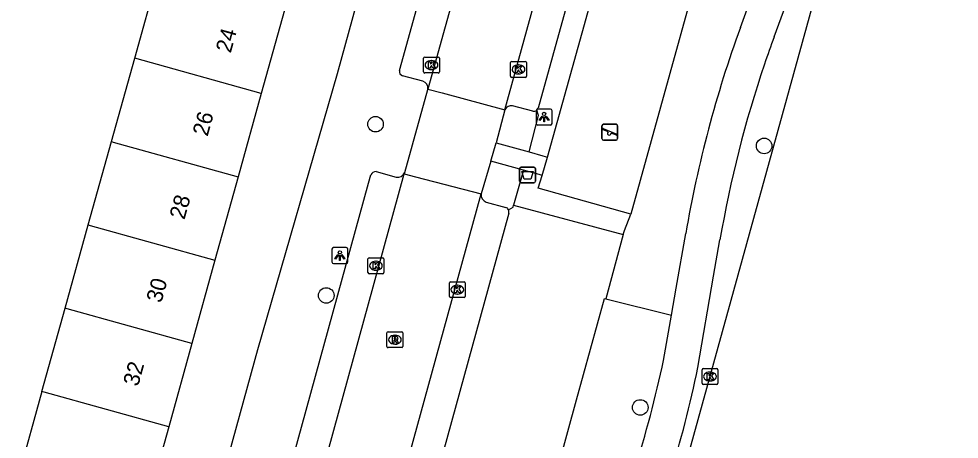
# Model space of a CAD drawing. Extents: x 162542 to 163144, y 380786 to 381511.
# Drawn here: x 163078.5 to 163137.6, y 381072.9 to 381099.3 of the extents above; entities that cross this region are included whole.
import ezdxf

# ---------------------------------------------------------------- set-up
doc = ezdxf.new("R2010")
doc.units = 0
for name, color, linetype in [('IMGEO_Afvalbak', 7, 'Continuous'), ('IMGEO_Berm_groen', 7, 'Continuous'), ('IMGEO_Boom', 7, 'Continuous'), ('IMGEO_Fietspad_gesloten', 7, 'Continuous'), ('IMGEO_Groenvoorziening', 7, 'Continuous'), ('IMGEO_Haag', 7, 'Continuous'), ('IMGEO_Hek', 7, 'Continuous'), ('IMGEO_Kolk', 7, 'Continuous'), ('IMGEO_Lichtpunt', 7, 'Continuous'), ('IMGEO_Pand', 7, 'Continuous'), ('IMGEO_Pand_nummerreeks', 7, 'Continuous'), ('IMGEO_Parkeervlak_open', 7, 'Continuous'), ('IMGEO_Rijbaan_lokaal_gesloten', 7, 'Continuous'), ('IMGEO_Rijbaan_lokaal_open', 7, 'Continuous'), ('IMGEO_Rioolput', 7, 'Continuous'), ('IMGEO_Speelvoorziening', 7, 'Continuous'), ('IMGEO_Voetpad_open', 7, 'Continuous')]:
    doc.layers.add(name, color=color, linetype=linetype)

msp = doc.modelspace()

# ---------------------------------------------------------------- linework, layer by layer
at = {"layer": 'IMGEO_Afvalbak'}
for p, q in [((163110.084, 381089.983), (163110.874, 381089.983)), ((163110.874, 381089.983), (163110.084, 381089.983)), ((163109.984, 381089.083), (163109.984, 381089.883)), ((163109.984, 381089.883), (163109.984, 381089.083)), ((163110.974, 381089.883), (163110.974, 381089.083)), ((163110.974, 381089.083), (163110.974, 381089.883)), ((163110.874, 381088.983), (163110.084, 381088.983)), ((163110.084, 381088.983), (163110.874, 381088.983))]:
    msp.add_line(p, q, dxfattribs=at)
msp.add_lwpolyline([(163110.127, 381089.697), (163110.831, 381089.697), (163110.682, 381089.227), (163110.276, 381089.227), (163110.127, 381089.697)], dxfattribs=at)
for centre, start, end in [((163110.084, 381089.883), 90, 180), ((163110.084, 381089.883), 90, 180), ((163110.874, 381089.883), 0, 90), ((163110.874, 381089.883), 360, 90), ((163110.084, 381089.083), 180, 270), ((163110.084, 381089.083), 180, 270), ((163110.874, 381089.083), 270, 0), ((163110.874, 381089.083), 270, 0)]:
    msp.add_arc(centre, 0.1, start, end, dxfattribs=at)
at = {"layer": 'IMGEO_Berm_groen'}
for points in [[(163123.149, 381109.351), (163116.979, 381087.012)], [(163109.281, 381087.299), (163109.576, 381087.467), (163109.61, 381087.588)], [(163116.483, 381085.73), (163115.4, 381081.696)], [(163090.379, 381018.056), (163091.195, 381019.449), (163095.086, 381024.701), (163097.994, 381027.705), (163100.091, 381030.633), (163101.545, 381033.297), (163102.955, 381036.558), (163113.57, 381075.334), (163115.317, 381081.716), (163115.4, 381081.696)], [(163115.4, 381081.696), (163119.528, 381080.672)]]:
    msp.add_lwpolyline(points, dxfattribs=at)
at = {"layer": 'IMGEO_Boom'}
for centre in [(163100.929, 381092.677), (163125.353, 381091.31), (163097.833, 381081.902), (163117.566, 381074.858)]:
    msp.add_circle(centre, 0.489, dxfattribs=at)
at = {"layer": 'IMGEO_Fietspad_gesloten'}
for points in [[(163123.86, 381098.765), (163126.379, 381105.719)], [(163125.975, 381098.165), (163128.416, 381104.806)], [(163119.528, 381080.672), (163119.826, 381082.372), (163120.427, 381085.8)], [(163121.184, 381077.371), (163122.18, 381083.116), (163122.575, 381085.397)], [(163119.028, 381077.818), (163119.528, 381080.672)]]:
    msp.add_lwpolyline(points, dxfattribs=at)
for centre, radius, start, end in [((163194.822, 381073.038), 75.482, 160.07208, 170.26597), ((163197.67, 381072.049), 76.304, 159.98479, 161.34559), ((163194.995, 381072.943), 73.483, 161.33919, 170.24235), ((163044.442, 381093.779), 76.275, 337.20621, 347.92112), ((163053.246, 381091.16), 69.323, 336.76744, 348.52643)]:
    msp.add_arc(centre, radius, start, end, dxfattribs=at)
at = {"layer": 'IMGEO_Groenvoorziening'}
for points in [[(163111.735, 381090.612), (163117.414, 381111.017)], [(163110.596, 381090.932), (163111.18, 381093.228), (163111.063, 381093.558)]]:
    msp.add_lwpolyline(points, dxfattribs=at)
at = {"layer": 'IMGEO_Haag'}
for points in [[(163110.227, 381089.781), (163109.61, 381087.588)], [(163116.979, 381087.012), (163111.158, 381088.662), (163111.393, 381089.458)], [(163109.61, 381087.588), (163116.483, 381085.73)], [(163116.483, 381085.73), (163116.579, 381085.993), (163116.979, 381087.012)]]:
    msp.add_lwpolyline(points, dxfattribs=at)
at = {"layer": 'IMGEO_Hek'}
for points in [[(163111.735, 381090.612), (163117.414, 381111.017), (163123.149, 381109.351)], [(163123.149, 381109.351), (163116.979, 381087.012)], [(163116.979, 381087.012), (163111.158, 381088.662), (163111.393, 381089.458)]]:
    msp.add_lwpolyline(points, dxfattribs=at)
at = {"layer": 'IMGEO_Kolk'}
for p, q in [((163103.947, 381095.972), (163103.947, 381096.824)), ((163104.022, 381096.898), (163104.874, 381096.898)), ((163104.435, 381096.678), (163104.46, 381096.678)), ((163104.948, 381096.824), (163104.948, 381095.972)), ((163109.415, 381095.698), (163109.415, 381096.55)), ((163109.49, 381096.624), (163110.342, 381096.624)), ((163110.416, 381096.55), (163110.416, 381095.698)), ((163104.874, 381095.898), (163104.022, 381095.898)), ((163104.458, 381096.118), (163104.433, 381096.118)), ((163109.903, 381096.404), (163109.928, 381096.404)), ((163110.342, 381095.624), (163109.49, 381095.624)), ((163109.926, 381095.844), (163109.901, 381095.844)), ((163100.456, 381083.346), (163100.456, 381084.198)), ((163100.531, 381084.272), (163101.383, 381084.272)), ((163100.944, 381084.052), (163100.969, 381084.052)), ((163101.457, 381084.198), (163101.457, 381083.346)), ((163100.967, 381083.492), (163100.942, 381083.492)), ((163101.383, 381083.272), (163100.531, 381083.272)), ((163105.572, 381081.841), (163105.572, 381082.693)), ((163105.647, 381082.767), (163106.499, 381082.767)), ((163106.06, 381082.547), (163106.085, 381082.547)), ((163106.573, 381082.693), (163106.573, 381081.841)), ((163106.499, 381081.767), (163105.647, 381081.767)), ((163106.083, 381081.987), (163106.058, 381081.987)), ((163121.45, 381076.377), (163121.45, 381077.229)), ((163121.525, 381077.303), (163122.377, 381077.303)), ((163121.938, 381077.083), (163121.963, 381077.083)), ((163122.451, 381077.229), (163122.451, 381076.377)), ((163121.961, 381076.523), (163121.936, 381076.523)), ((163122.377, 381076.303), (163121.525, 381076.303))]:
    msp.add_line(p, q, dxfattribs=at)
for points in [[(163103.947, 381095.972), (163103.947, 381096.824)], [(163104.022, 381096.898), (163104.874, 381096.898)], [(163104.268, 381096.598), (163104.391, 381096.598), (163104.391, 381096.447), (163104.521, 381096.598), (163104.685, 381096.598), (163104.539, 381096.447), (163104.692, 381096.198), (163104.54, 381096.198), (163104.455, 381096.362), (163104.391, 381096.295), (163104.391, 381096.198), (163104.268, 381096.198), (163104.268, 381096.598)], [(163104.948, 381096.824), (163104.948, 381095.972)], [(163109.415, 381095.698), (163109.415, 381096.55)], [(163109.49, 381096.624), (163110.342, 381096.624)], [(163110.416, 381096.55), (163110.416, 381095.698)], [(163104.874, 381095.898), (163104.022, 381095.898)], [(163109.736, 381096.324), (163109.859, 381096.324), (163109.859, 381096.173), (163109.989, 381096.324), (163110.153, 381096.324), (163110.007, 381096.173), (163110.16, 381095.924), (163110.008, 381095.924), (163109.923, 381096.088), (163109.859, 381096.021), (163109.859, 381095.924), (163109.736, 381095.924), (163109.736, 381096.324)], [(163110.342, 381095.624), (163109.49, 381095.624)], [(163100.456, 381083.346), (163100.456, 381084.198)], [(163100.531, 381084.272), (163101.383, 381084.272)], [(163101.457, 381084.198), (163101.457, 381083.346)], [(163100.777, 381083.972), (163100.9, 381083.972), (163100.9, 381083.821), (163101.03, 381083.972), (163101.194, 381083.972), (163101.048, 381083.821), (163101.201, 381083.572), (163101.049, 381083.572), (163100.964, 381083.736), (163100.9, 381083.669), (163100.9, 381083.572), (163100.777, 381083.572), (163100.777, 381083.972)], [(163101.383, 381083.272), (163100.531, 381083.272)], [(163105.572, 381081.841), (163105.572, 381082.693)], [(163105.647, 381082.767), (163106.499, 381082.767)], [(163105.893, 381082.467), (163106.016, 381082.467), (163106.016, 381082.316), (163106.146, 381082.467), (163106.31, 381082.467), (163106.164, 381082.316), (163106.317, 381082.067), (163106.165, 381082.067), (163106.08, 381082.231), (163106.016, 381082.164), (163106.016, 381082.067), (163105.893, 381082.067), (163105.893, 381082.467)], [(163106.573, 381082.693), (163106.573, 381081.841)], [(163106.499, 381081.767), (163105.647, 381081.767)], [(163121.45, 381076.377), (163121.45, 381077.229)], [(163121.525, 381077.303), (163122.377, 381077.303)], [(163121.771, 381077.003), (163121.894, 381077.003), (163121.894, 381076.852), (163122.024, 381077.003), (163122.188, 381077.003), (163122.042, 381076.852), (163122.195, 381076.603), (163122.043, 381076.603), (163121.958, 381076.767), (163121.894, 381076.7), (163121.894, 381076.603), (163121.771, 381076.603), (163121.771, 381077.003)], [(163122.451, 381077.229), (163122.451, 381076.377)], [(163122.377, 381076.303), (163121.525, 381076.303)]]:
    msp.add_lwpolyline(points, dxfattribs=at)
for centre, start, end in [((163104.024, 381096.822), 91.55205, 178.44795), ((163104.024, 381096.822), 91.55205, 178.44795), ((163104.872, 381096.822), 1.55205, 88.44795), ((163104.872, 381096.822), 1.55205, 88.44795), ((163109.492, 381096.548), 91.55205, 178.44795), ((163109.492, 381096.548), 91.55205, 178.44795), ((163110.34, 381096.548), 1.55205, 88.44795), ((163110.34, 381096.548), 1.55205, 88.44795), ((163104.024, 381095.974), 181.55205, 268.44795), ((163104.024, 381095.974), 181.55205, 268.44795), ((163104.872, 381095.974), 271.55205, 358.44795), ((163104.872, 381095.974), 271.55205, 358.44795), ((163109.492, 381095.7), 181.55205, 268.44795), ((163109.492, 381095.7), 181.55205, 268.44795), ((163110.34, 381095.7), 271.55205, 358.44795), ((163110.34, 381095.7), 271.55205, 358.44795), ((163100.533, 381084.196), 91.55205, 178.44795), ((163100.533, 381084.196), 91.55205, 178.44795), ((163101.381, 381084.196), 1.55205, 88.44795), ((163101.381, 381084.196), 1.55205, 88.44795), ((163100.533, 381083.348), 181.55205, 268.44795), ((163100.533, 381083.348), 181.55205, 268.44795), ((163101.381, 381083.348), 271.55205, 358.44795), ((163101.381, 381083.348), 271.55205, 358.44795), ((163105.649, 381082.691), 91.55205, 178.44795), ((163105.649, 381082.691), 91.55205, 178.44795), ((163106.497, 381082.691), 1.55205, 88.44795), ((163106.497, 381082.691), 1.55205, 88.44795), ((163105.649, 381081.843), 181.55205, 268.44795), ((163105.649, 381081.843), 181.55205, 268.44795), ((163106.497, 381081.843), 271.55205, 358.44795), ((163106.497, 381081.843), 271.55205, 358.44795), ((163121.527, 381077.227), 91.55205, 178.44795), ((163121.527, 381077.227), 91.55205, 178.44795), ((163122.375, 381077.227), 1.55205, 88.44795), ((163122.375, 381077.227), 1.55205, 88.44795), ((163121.527, 381076.379), 181.55205, 268.44795), ((163121.527, 381076.379), 181.55205, 268.44795), ((163122.375, 381076.379), 271.55205, 358.44795), ((163122.375, 381076.379), 271.55205, 358.44795)]:
    msp.add_arc(centre, 0.0765, start, end, dxfattribs=at)
for centre, major_axis, ratio, start_param, end_param in [((163104.434, 381096.398), (-0.387, 0.002), 0.722429, 4.712389, 7.853982), ((163104.459, 381096.398), (-0.39, 0.002), 0.717154, 1.570796, 4.712389), ((163109.902, 381096.124), (-0.387, 0.002), 0.722429, 4.712389, 7.853982), ((163109.927, 381096.124), (-0.39, 0.002), 0.717154, 1.570796, 4.712389), ((163100.943, 381083.772), (-0.387, 0.002), 0.722429, 4.712389, 7.853982), ((163100.968, 381083.772), (-0.39, 0.002), 0.717154, 1.570796, 4.712389), ((163106.059, 381082.267), (-0.387, 0.002), 0.722429, 4.712389, 7.853982), ((163106.084, 381082.267), (-0.39, 0.002), 0.717154, 1.570796, 4.712389), ((163121.937, 381076.803), (-0.387, 0.002), 0.722429, 4.712389, 7.853982), ((163121.962, 381076.803), (-0.39, 0.002), 0.717154, 1.570796, 4.712389)]:
    msp.add_ellipse(centre, major_axis=major_axis, ratio=ratio, start_param=start_param, end_param=end_param, dxfattribs=at)
at = {"layer": 'IMGEO_Lichtpunt'}
for p, q in [((163111.026, 381093.528), (163111.026, 381092.721)), ((163111.026, 381093.528), (163111.026, 381092.721)), ((163111.928, 381093.623), (163111.12, 381093.623)), ((163111.928, 381093.623), (163111.12, 381093.623)), ((163112.022, 381092.721), (163112.022, 381093.528)), ((163112.022, 381092.721), (163112.022, 381093.528)), ((163111.12, 381092.627), (163111.928, 381092.627)), ((163111.12, 381092.627), (163111.928, 381092.627)), ((163098.192, 381084.816), (163098.192, 381084.009)), ((163098.192, 381084.816), (163098.192, 381084.009)), ((163099.094, 381084.911), (163098.286, 381084.911)), ((163099.094, 381084.911), (163098.286, 381084.911)), ((163099.188, 381084.009), (163099.188, 381084.816)), ((163099.188, 381084.009), (163099.188, 381084.816)), ((163098.286, 381083.915), (163099.094, 381083.915)), ((163098.286, 381083.915), (163099.094, 381083.915))]:
    msp.add_line(p, q, dxfattribs=at)
for points in [[(163111.4, 381093.192), (163111.439, 381093.164), (163111.251, 381092.902), (163111.213, 381092.929), (163111.4, 381093.192)], [(163111.502, 381093.144), (163111.549, 381093.144), (163111.549, 381092.822), (163111.502, 381092.822), (163111.502, 381093.144)], [(163111.612, 381093.164), (163111.65, 381093.191), (163111.837, 381092.929), (163111.798, 381092.901), (163111.612, 381093.164)], [(163098.566, 381084.48), (163098.605, 381084.452), (163098.417, 381084.19), (163098.379, 381084.217), (163098.566, 381084.48)], [(163098.668, 381084.432), (163098.715, 381084.432), (163098.715, 381084.11), (163098.668, 381084.11), (163098.668, 381084.432)], [(163098.778, 381084.452), (163098.816, 381084.479), (163099.003, 381084.217), (163098.964, 381084.189), (163098.778, 381084.452)]]:
    msp.add_lwpolyline(points, dxfattribs=at)
for centre in [(163111.525, 381093.326), (163098.691, 381084.614)]:
    msp.add_circle(centre, 0.0994, dxfattribs=at)
for centre, start, end in [((163111.12, 381093.528), 90, 180), ((163111.12, 381093.528), 90, 180), ((163111.928, 381093.528), 0, 90), ((163111.928, 381093.528), 0, 90), ((163111.12, 381092.721), 180, 270), ((163111.12, 381092.721), 180, 270), ((163111.928, 381092.721), 270, 0), ((163111.928, 381092.721), 270, 360), ((163098.286, 381084.816), 90, 180), ((163098.286, 381084.816), 90, 180), ((163099.094, 381084.816), 0, 90), ((163099.094, 381084.816), 0, 90), ((163098.286, 381084.009), 180, 270), ((163098.286, 381084.009), 180, 270), ((163099.094, 381084.009), 270, 0), ((163099.094, 381084.009), 270, 360)]:
    msp.add_arc(centre, 0.0946, start, end, dxfattribs=at)
at = {"layer": 'IMGEO_Pand'}
for points in [[(163085.795, 381096.822), (163087.252, 381102.063)], [(163095.205, 381099.852), (163093.75, 381094.611)], [(163084.339, 381091.582), (163085.795, 381096.822)], [(163093.75, 381094.611), (163085.795, 381096.822)], [(163093.75, 381094.611), (163092.295, 381089.37)], [(163082.882, 381086.341), (163084.339, 381091.582)], [(163084.339, 381091.582), (163084.441, 381091.554), (163092.295, 381089.37)], [(163092.295, 381089.37), (163090.84, 381084.129)], [(163081.426, 381081.1), (163082.882, 381086.341)], [(163082.882, 381086.341), (163082.997, 381086.309), (163090.84, 381084.129)], [(163090.84, 381084.129), (163089.386, 381078.888)], [(163079.969, 381075.86), (163081.426, 381081.1)], [(163089.386, 381078.888), (163081.553, 381081.065), (163081.426, 381081.1)], [(163089.386, 381078.888), (163087.931, 381073.647)], [(163079.969, 381075.86), (163078.513, 381070.62)], [(163087.931, 381073.647), (163080.11, 381075.821), (163079.969, 381075.86)], [(163087.931, 381073.647), (163086.476, 381068.406)]]:
    msp.add_lwpolyline(points, dxfattribs=at)
at = {"layer": 'IMGEO_Parkeervlak_open'}
for points in [[(163116.047, 381111.414), (163115.864, 381110.721), (163111.152, 381093.682)], [(163110.815, 381093.493), (163109.544, 381093.839)], [(163107.893, 381087.77), (163109.119, 381087.439)], [(163109.3, 381087.086), (163093.379, 381029.068), (163091.294, 381021.437), (163090.379, 381018.056)]]:
    msp.add_lwpolyline(points, dxfattribs=at)
for centre, radius, start, end in [((163109.468, 381093.405), 0.441, 80.0781, 157.42502), ((163110.87, 381093.79), 0.302, 259.53052, 309.84285), ((163110.865, 381093.794), 0.308, 310.0039, 338.65892), ((163108.09, 381088.256), 0.525, 174.85461, 247.8914), ((163109.031, 381087.173), 0.28, 26.70239, 71.63061), ((163109.024, 381087.169), 0.288, 343.33638, 26.85842)]:
    msp.add_arc(centre, radius, start, end, dxfattribs=at)
at = {"layer": 'IMGEO_Rijbaan_lokaal_gesloten'}
msp.add_lwpolyline([(163137.61, 381134.315), (163137.557, 381133.07), (163136.979, 381131.279), (163105.941, 381018.863), (163101.737, 381003.421), (163101.031, 381000.829)], dxfattribs=at)
at = {"layer": 'IMGEO_Rijbaan_lokaal_open'}
for points in [[(163116.194, 381138.143), (163112.827, 381125.89), (163104.211, 381094.881)], [(163109.061, 381093.574), (163121.145, 381137.399)], [(163104.211, 381094.881), (163104.203, 381094.844), (163102.742, 381089.624)], [(163104.211, 381094.881), (163105.122, 381094.652), (163109.061, 381093.574)], [(163109.061, 381093.574), (163108.507, 381091.513)], [(163108.167, 381090.341), (163108.171, 381090.354), (163108.507, 381091.513)], [(163108.167, 381090.341), (163107.568, 381088.303)], [(163084.559, 381023.291), (163102.722, 381089.551)], [(163102.742, 381089.624), (163102.722, 381089.551)], [(163102.722, 381089.551), (163103.434, 381089.372), (163107.568, 381088.303)], [(163089.373, 381021.916), (163091.439, 381029.59), (163093.215, 381036.056), (163098.85, 381056.569), (163107.568, 381088.303)]]:
    msp.add_lwpolyline(points, dxfattribs=at)
at = {"layer": 'IMGEO_Rioolput'}
for p, q in [((163101.649, 381078.693), (163101.649, 381079.545)), ((163101.724, 381079.619), (163102.576, 381079.619)), ((163102.137, 381079.399), (163102.162, 381079.399)), ((163102.65, 381079.545), (163102.65, 381078.693)), ((163102.16, 381078.839), (163102.135, 381078.839)), ((163102.576, 381078.619), (163101.724, 381078.619))]:
    msp.add_line(p, q, dxfattribs=at)
for points in [[(163101.649, 381078.693), (163101.649, 381079.545)], [(163101.724, 381079.619), (163102.576, 381079.619)], [(163102.65, 381079.545), (163102.65, 381078.693)], [(163102.238, 381079.317), (163101.986, 381079.319), (163101.986, 381078.919)], [(163101.986, 381078.919), (163102.11, 381078.919), (163102.11, 381079.081), (163102.121, 381079.081)], [(163102.164, 381079.238), (163102.11, 381079.238), (163102.11, 381079.157)], [(163102.11, 381079.157), (163102.162, 381079.157)], [(163102.168, 381079.052), (163102.239, 381078.919), (163102.379, 381078.919), (163102.314, 381079.045)], [(163102.576, 381078.619), (163101.724, 381078.619)]]:
    msp.add_lwpolyline(points, dxfattribs=at)
for centre, radius, start, end in [((163101.726, 381079.543), 0.0765, 91.55205, 178.44795), ((163101.726, 381079.543), 0.0765, 91.55205, 178.44795), ((163102.574, 381079.543), 0.0765, 1.55205, 88.44795), ((163102.574, 381079.543), 0.0765, 1.55205, 88.44795), ((163102.12, 381079.028), 0.0533, 26.02933, 88.69889), ((163102.146, 381079.346), 0.19, 274.7715, 282.96867), ((163102.17, 381079.142), 0.0964, 77.00612, 93.18647), ((163102.184, 381079.199), 0.0378, 276.66336, 79.67722), ((163102.237, 381079.207), 0.109, 350.36119, 89.41601), ((163102.235, 381079.207), 0.112, 277.58423, 350.98172), ((163102.219, 381078.992), 0.108, 29.51342, 73.79051), ((163101.726, 381078.695), 0.0765, 181.55205, 268.44795), ((163101.726, 381078.695), 0.0765, 181.55205, 268.44795), ((163102.574, 381078.695), 0.0765, 271.55205, 358.44795), ((163102.574, 381078.695), 0.0765, 271.55205, 358.44795)]:
    msp.add_arc(centre, radius, start, end, dxfattribs=at)
for centre, major_axis, ratio, start_param, end_param in [((163102.136, 381079.119), (-0.387, 0.002), 0.722429, 4.712389, 7.853982), ((163102.161, 381079.119), (-0.39, 0.002), 0.717154, 1.570796, 4.712389)]:
    msp.add_ellipse(centre, major_axis=major_axis, ratio=ratio, start_param=start_param, end_param=end_param, dxfattribs=at)
at = {"layer": 'IMGEO_Speelvoorziening'}
for p, q in [((163115.157, 381091.773), (163115.157, 381092.573)), ((163115.157, 381092.573), (163115.157, 381091.773)), ((163115.54, 381092.201), (163115.201, 381092.338)), ((163115.226, 381092.398), (163116.102, 381092.045)), ((163115.257, 381092.673), (163116.047, 381092.673)), ((163116.047, 381092.673), (163115.257, 381092.673)), ((163116.147, 381092.573), (163116.147, 381091.773)), ((163116.147, 381091.773), (163116.147, 381092.573)), ((163116.078, 381091.985), (163115.738, 381092.122)), ((163116.047, 381091.673), (163115.257, 381091.673)), ((163115.257, 381091.673), (163116.047, 381091.673))]:
    msp.add_line(p, q, dxfattribs=at)
for centre, radius, start, end in [((163115.257, 381092.573), 0.1, 90, 180), ((163115.257, 381092.573), 0.1, 90, 180), ((163115.214, 381092.368), 0.0327, 68.07798, 248.07798), ((163116.047, 381092.573), 0.1, 0, 90), ((163116.047, 381092.573), 0.1, 360, 90), ((163115.257, 381091.773), 0.1, 180, 270), ((163115.257, 381091.773), 0.1, 180, 270), ((163115.619, 381092.111), 0.12, 130.99278, 5.16318), ((163116.047, 381091.773), 0.1, 270, 0), ((163116.047, 381091.773), 0.1, 270, 0), ((163116.09, 381092.015), 0.0327, 248.07798, 68.07798)]:
    msp.add_arc(centre, radius, start, end, dxfattribs=at)
at = {"layer": 'IMGEO_Voetpad_open'}
for points in [[(163102.441, 381096.055), (163110.966, 381126.784), (163113.442, 381135.707)], [(163079.113, 381025.409), (163089.044, 381062.198), (163093.539, 381078.503), (163098.537, 381095.857), (163108.607, 381132.594), (163108.43, 381133.686), (163107.841, 381134.207), (163105.012, 381135.183)], [(163103.903, 381095.382), (163102.625, 381095.727)], [(163108.507, 381091.513), (163110.596, 381090.932)], [(163110.596, 381090.932), (163111.454, 381090.693), (163111.735, 381090.612)], [(163111.393, 381089.458), (163111.735, 381090.612)], [(163110.227, 381089.781), (163108.167, 381090.341)], [(163083.391, 381026.615), (163086.585, 381038.264), (163100.487, 381088.976), (163100.631, 381089.497)], [(163100.965, 381089.692), (163102.224, 381089.338)], [(163111.393, 381089.458), (163111.216, 381089.505), (163110.227, 381089.781)]]:
    msp.add_lwpolyline(points, dxfattribs=at)
for centre, radius, start, end in [((163102.703, 381095.986), 0.271, 165.35739, 253.22533), ((163103.772, 381094.956), 0.445, 350.27421, 72.88974), ((163100.952, 381089.33), 0.362, 88.00022, 152.55531), ((163102.314, 381089.788), 0.459, 258.73708, 339.07116)]:
    msp.add_arc(centre, radius, start, end, dxfattribs=at)

# ---------------------------------------------------------------- texts
at = {"layer": 'IMGEO_Pand_nummerreeks'}
for s, p in [('24', (163091.828, 381097.109)), ('26', (163090.373, 381091.868)), ('28', (163088.92, 381086.63)), ('30', (163087.465, 381081.389)), ('32', (163086.008, 381076.142))]:
    msp.add_text(s, height=1, rotation=74.48624, dxfattribs=at).set_placement(p)

doc.saveas('drawing.dxf')
